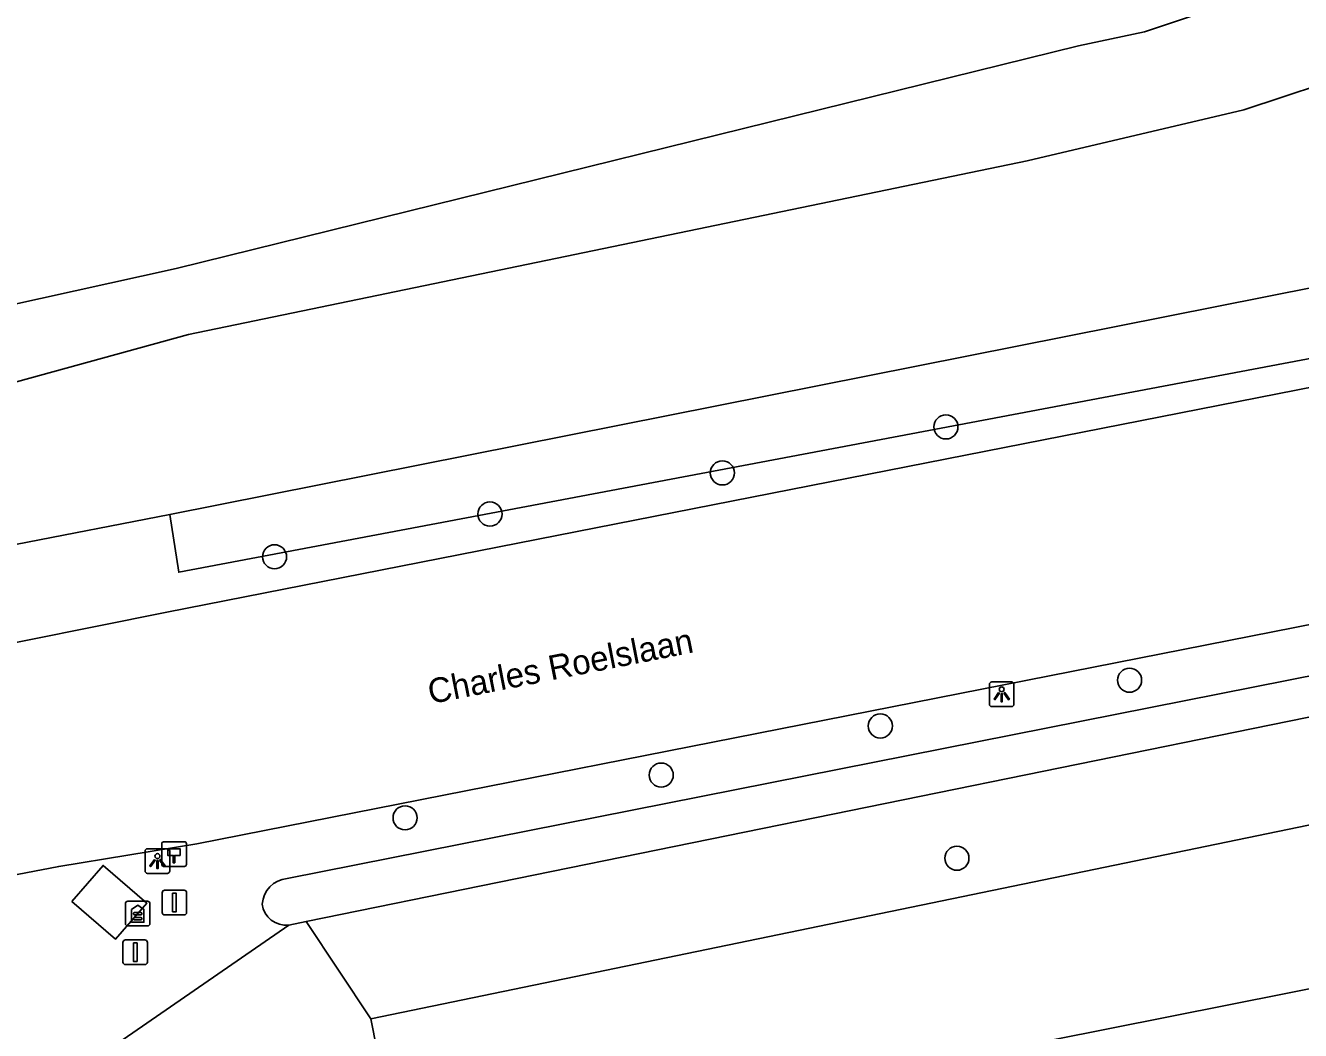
# Model space of a CAD drawing. Extents: x 160203 to 161526, y 379529 to 381797.
# Drawn here: x 160929.4 to 160981.1, y 379927.3 to 379968.1 of the extents above; entities that cross this region are included whole.
import ezdxf

# ---------------------------------------------------------------- set-up
doc = ezdxf.new("R2010")
doc.units = 0
for name, color, linetype in [('IMGEO_Boom', 7, 'Continuous'), ('IMGEO_Groenvoorziening', 7, 'Continuous'), ('IMGEO_Hectometerpaal', 7, 'Continuous'), ('IMGEO_Hek', 7, 'Continuous'), ('IMGEO_Lichtpunt', 7, 'Continuous'), ('IMGEO_Loofbos', 7, 'Continuous'), ('IMGEO_Openbare_ruimte_label', 7, 'Continuous'), ('IMGEO_Reclamezuil', 7, 'Continuous'), ('IMGEO_Rijbaan_lokaal_open', 7, 'Continuous'), ('IMGEO_Vlaggenmast', 7, 'Continuous'), ('IMGEO_Voetpad_onverhard', 7, 'Continuous'), ('IMGEO_Waterloop', 7, 'Continuous')]:
    doc.layers.add(name, color=color, linetype=linetype)

msp = doc.modelspace()

# ---------------------------------------------------------------- linework, layer by layer
at = {"layer": 'IMGEO_Boom'}
for centre in [(160966.71, 379951.778), (160957.643, 379949.911), (160948.217, 379948.242), (160939.479, 379946.506), (160974.159, 379941.498), (160964.05, 379939.64), (160955.163, 379937.648), (160944.773, 379935.913), (160967.156, 379934.274)]:
    msp.add_circle(centre, 0.489, dxfattribs=at)
at = {"layer": 'IMGEO_Groenvoorziening'}
msp.add_lwpolyline([(160931.262, 379932.519), (160932.525, 379933.982), (160934.297, 379932.453), (160933.929, 379932.027), (160933.033, 379930.989), (160931.262, 379932.519)], dxfattribs=at)
at = {"layer": 'IMGEO_Hectometerpaal'}
for p, q in [((160934.905, 379934.854), (160934.905, 379934.013)), ((160934.905, 379934.854), (160934.905, 379934.013)), ((160935.821, 379934.938), (160934.98, 379934.938)), ((160935.821, 379934.938), (160934.98, 379934.938)), ((160935.905, 379934.022), (160935.905, 379934.863)), ((160935.905, 379934.022), (160935.905, 379934.863)), ((160934.989, 379933.938), (160935.83, 379933.938)), ((160934.989, 379933.938), (160935.83, 379933.938))]:
    msp.add_line(p, q, dxfattribs=at)
msp.add_lwpolyline([(160935.43, 379934.082), (160935.37, 379934.082), (160935.37, 379934.387), (160935.15, 379934.387), (160935.15, 379934.656), (160935.65, 379934.656), (160935.65, 379934.387), (160935.43, 379934.387), (160935.43, 379934.082)], dxfattribs=at)
for centre, start, end in [((160934.983, 379934.86), 92.4484, 184.2845), ((160934.983, 379934.86), 92.4484, 184.2845), ((160935.827, 379934.86), 2.4484, 94.2845), ((160935.827, 379934.86), 2.4484, 94.2845), ((160934.983, 379934.016), 182.4484, 274.2845), ((160934.983, 379934.016), 182.4484, 274.2845), ((160935.827, 379934.016), 272.4484, 4.2845), ((160935.827, 379934.016), 272.4484, 4.2845)]:
    msp.add_arc(centre, 0.0779, start, end, dxfattribs=at)
at = {"layer": 'IMGEO_Hek'}
msp.add_lwpolyline([(161000, 379932.662), (160951.544, 379923.025), (160959.272, 379883.804)], dxfattribs=at)
at = {"layer": 'IMGEO_Lichtpunt'}
for p, q in [((160968.474, 379941.331), (160968.474, 379940.524)), ((160968.474, 379941.331), (160968.474, 379940.524)), ((160969.376, 379941.426), (160968.568, 379941.426)), ((160969.376, 379941.426), (160968.568, 379941.426)), ((160969.47, 379940.524), (160969.47, 379941.331)), ((160969.47, 379940.524), (160969.47, 379941.331)), ((160968.568, 379940.43), (160969.376, 379940.43)), ((160968.568, 379940.43), (160969.376, 379940.43)), ((160934.231, 379934.561), (160934.231, 379933.754)), ((160934.231, 379934.561), (160934.231, 379933.754)), ((160935.133, 379934.656), (160934.325, 379934.656)), ((160935.133, 379934.656), (160934.325, 379934.656)), ((160935.227, 379933.754), (160935.227, 379934.561)), ((160935.227, 379933.754), (160935.227, 379934.561)), ((160934.325, 379933.66), (160935.133, 379933.66)), ((160934.325, 379933.66), (160935.133, 379933.66))]:
    msp.add_line(p, q, dxfattribs=at)
for points in [[(160968.848, 379940.995), (160968.887, 379940.967), (160968.699, 379940.705), (160968.661, 379940.732), (160968.848, 379940.995)], [(160968.95, 379940.947), (160968.997, 379940.947), (160968.997, 379940.625), (160968.95, 379940.625), (160968.95, 379940.947)], [(160969.06, 379940.967), (160969.098, 379940.994), (160969.285, 379940.732), (160969.246, 379940.704), (160969.06, 379940.967)], [(160934.605, 379934.225), (160934.644, 379934.197), (160934.456, 379933.935), (160934.418, 379933.962), (160934.605, 379934.225)], [(160934.707, 379934.177), (160934.754, 379934.177), (160934.754, 379933.855), (160934.707, 379933.855), (160934.707, 379934.177)], [(160934.817, 379934.197), (160934.855, 379934.224), (160935.042, 379933.962), (160935.003, 379933.934), (160934.817, 379934.197)]]:
    msp.add_lwpolyline(points, dxfattribs=at)
for centre in [(160968.973, 379941.129), (160934.73, 379934.359)]:
    msp.add_circle(centre, 0.0994, dxfattribs=at)
for centre, start, end in [((160968.568, 379941.331), 90, 180), ((160968.568, 379941.331), 90, 180), ((160969.376, 379941.331), 0, 90), ((160969.376, 379941.331), 0, 90), ((160968.568, 379940.524), 180, 270), ((160968.568, 379940.524), 180, 270), ((160969.376, 379940.524), 270, 0), ((160969.376, 379940.524), 270, 360), ((160934.325, 379934.561), 90, 180), ((160934.325, 379934.561), 90, 180), ((160935.133, 379934.561), 0, 90), ((160935.133, 379934.561), 0, 90), ((160934.325, 379933.754), 180, 270), ((160934.325, 379933.754), 180, 270), ((160935.133, 379933.754), 270, 0), ((160935.133, 379933.754), 270, 360)]:
    msp.add_arc(centre, 0.0946, start, end, dxfattribs=at)
at = {"layer": 'IMGEO_Loofbos'}
for points in [[(160935.239, 379948.227), (160922.706, 379945.785), (160921.668, 379948.198)], [(160943.379, 379927.759), (161000, 379939.454), (161011.409, 379941.81), (161024.194, 379944.451)], [(161024.194, 379944.451), (161025.245, 379937.898), (161013.069, 379935.373), (161000, 379932.662), (160951.544, 379923.025), (160959.272, 379883.804), (160959.428, 379883.014)], [(160933.604, 379881.066), (160925.646, 379921.61), (160940.056, 379931.56)], [(160943.379, 379927.759), (160940.767, 379931.705)], [(160952.452, 379881.869), (160943.379, 379927.759)]]:
    msp.add_lwpolyline(points, dxfattribs=at)
at = {"layer": 'IMGEO_Reclamezuil'}
for p, q in [((160933.431, 379932.431), (160933.431, 379931.623)), ((160933.431, 379932.431), (160933.431, 379931.623)), ((160934.333, 379932.525), (160933.525, 379932.525)), ((160934.333, 379932.525), (160933.525, 379932.525)), ((160934.427, 379931.623), (160934.427, 379932.431)), ((160934.427, 379931.623), (160934.427, 379932.431)), ((160934.06, 379932.067), (160933.798, 379932.067)), ((160933.798, 379931.98), (160934.06, 379931.98)), ((160934.06, 379931.865), (160933.798, 379931.865)), ((160933.525, 379931.529), (160934.333, 379931.529)), ((160933.525, 379931.529), (160934.333, 379931.529)), ((160933.798, 379931.778), (160934.06, 379931.778))]:
    msp.add_line(p, q, dxfattribs=at)
msp.add_lwpolyline([(160933.679, 379932.198), (160933.929, 379932.368), (160934.179, 379932.198), (160934.179, 379931.675), (160933.679, 379931.675), (160933.679, 379932.198)], dxfattribs=at)
for centre, radius, start, end in [((160933.525, 379932.431), 0.0946, 90, 180), ((160933.525, 379932.431), 0.0946, 90, 180), ((160934.333, 379932.431), 0.0946, 0, 90), ((160934.333, 379932.431), 0.0946, 0, 90), ((160933.798, 379932.024), 0.0436, 89.974, 270.026), ((160933.798, 379931.821), 0.0436, 89.974, 270.026), ((160934.06, 379932.024), 0.0436, 269.974, 90.026), ((160934.06, 379931.821), 0.0436, 269.974, 90.026), ((160933.525, 379931.623), 0.0946, 180, 270), ((160933.525, 379931.623), 0.0946, 180, 270), ((160934.333, 379931.623), 0.0946, 270, 0), ((160934.333, 379931.623), 0.0946, 270, 0)]:
    msp.add_arc(centre, radius, start, end, dxfattribs=at)
at = {"layer": 'IMGEO_Rijbaan_lokaal_open'}
for points in [[(160926.483, 379942.53), (160935.112, 379944.265), (160989.654, 379954.98), (160999.998, 379956.482), (161003.088, 379956.98), (161017.577, 379958.366)], [(161026.674, 379952.839), (161013.911, 379950.345), (161000, 379947.411), (160936.325, 379934.86), (160930.729, 379933.941), (160927.405, 379933.308)]]:
    msp.add_lwpolyline(points, dxfattribs=at)
at = {"layer": 'IMGEO_Vlaggenmast'}
for p, q in [((160935.022, 379932.974), (160935.812, 379932.974)), ((160935.812, 379932.974), (160935.022, 379932.974)), ((160934.922, 379932.074), (160934.922, 379932.874)), ((160934.922, 379932.874), (160934.922, 379932.074)), ((160935.912, 379932.874), (160935.912, 379932.074)), ((160935.912, 379932.074), (160935.912, 379932.874)), ((160935.812, 379931.974), (160935.022, 379931.974)), ((160935.022, 379931.974), (160935.812, 379931.974)), ((160933.332, 379930.058), (160933.332, 379930.858)), ((160933.332, 379930.858), (160933.332, 379930.058)), ((160933.432, 379930.958), (160934.222, 379930.958)), ((160934.222, 379930.958), (160933.432, 379930.958)), ((160934.322, 379930.858), (160934.322, 379930.058)), ((160934.322, 379930.058), (160934.322, 379930.858)), ((160934.222, 379929.958), (160933.432, 379929.958)), ((160933.432, 379929.958), (160934.222, 379929.958))]:
    msp.add_line(p, q, dxfattribs=at)
for points in [[(160935.342, 379932.849), (160935.492, 379932.849), (160935.492, 379932.099), (160935.342, 379932.099), (160935.342, 379932.849)], [(160933.752, 379930.833), (160933.902, 379930.833), (160933.902, 379930.083), (160933.752, 379930.083), (160933.752, 379930.833)]]:
    msp.add_lwpolyline(points, dxfattribs=at)
for centre, start, end in [((160935.022, 379932.874), 90, 180), ((160935.022, 379932.874), 90, 180), ((160935.812, 379932.874), 0, 90), ((160935.812, 379932.874), 360, 90), ((160935.022, 379932.074), 180, 270), ((160935.022, 379932.074), 180, 270), ((160935.812, 379932.074), 270, 0), ((160935.812, 379932.074), 270, 0), ((160933.432, 379930.858), 90, 180), ((160933.432, 379930.858), 90, 180), ((160934.222, 379930.858), 0, 90), ((160934.222, 379930.858), 360, 90), ((160933.432, 379930.058), 180, 270), ((160933.432, 379930.058), 180, 270), ((160934.222, 379930.058), 270, 0), ((160934.222, 379930.058), 270, 0)]:
    msp.add_arc(centre, 0.1, start, end, dxfattribs=at)
at = {"layer": 'IMGEO_Voetpad_onverhard'}
for points in [[(160980.332, 379970.199), (160979.298, 379969.591), (160977.079, 379968.582), (160974.767, 379967.81), (160972.092, 379967.237), (160935.494, 379958.213), (160923.188, 379955.482), (160922.449, 379955.516), (160921, 379955.813), (160920.602, 379955.987)], [(161019.862, 379967.505), (160990.026, 379967.436), (160987.186, 379967.088), (160983.541, 379966.218), (160978.788, 379964.646), (160970.004, 379962.58), (160935.992, 379955.526), (160925.518, 379952.646), (160924.211, 379951.846), (160923.099, 379950.792), (160922.23, 379949.53), (160921.668, 379948.198)]]:
    msp.add_lwpolyline(points, dxfattribs=at)
at = {"layer": 'IMGEO_Waterloop'}
for points in [[(160935.239, 379948.227), (160997.906, 379960.687)], [(161000, 379958.372), (160998.654, 379957.795), (160935.592, 379945.881), (160935.239, 379948.227)], [(160939.993, 379933.455), (160991.806, 379943.722), (161000, 379945.518)], [(160940.767, 379931.705), (160995.56, 379942.876)], [(160940.767, 379931.705), (160940.056, 379931.56)]]:
    msp.add_lwpolyline(points, dxfattribs=at)
for centre, radius, start, end in [((160940.109, 379932.328), 1.132, 95.869, 176.0749), ((160939.955, 379932.54), 0.986, 187.8368, 275.8629)]:
    msp.add_arc(centre, radius, start, end, dxfattribs=at)

# ---------------------------------------------------------------- texts
at = {"layer": 'IMGEO_Openbare_ruimte_label'}
msp.add_text('Charles Roelslaan', height=1, rotation=11.1301, dxfattribs=at).set_placement((160945.807, 379940.527))

doc.saveas('drawing.dxf')
